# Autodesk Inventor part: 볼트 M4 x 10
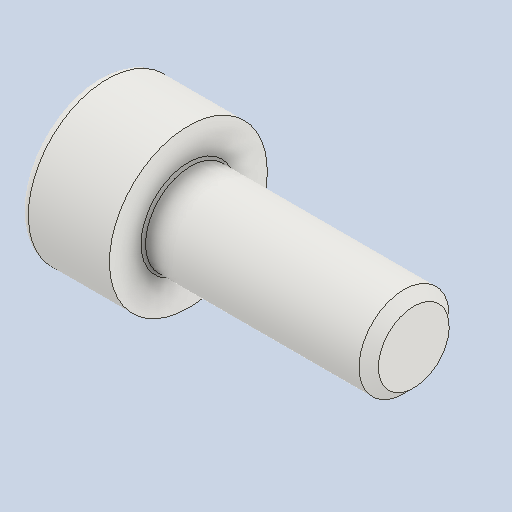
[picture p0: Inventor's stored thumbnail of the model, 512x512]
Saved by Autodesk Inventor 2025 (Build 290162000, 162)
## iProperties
Created: 2024-07
Part Number: 볼트 M4 x 10
Material: 강철, 연강
Description: 6각머리 태핑 나사
Document SubType Name: Modeling
Designer: SAMSUNG
Density: 7.86 g/cm^3
Appearance: 기본값
Author: jhkim
Revision Number: 1
Sending System: Autodesk Inventor 2025
Preprocessor: ST-DEVELOPER v20
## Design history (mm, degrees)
feature "Solid1"
node "솔리드1"
